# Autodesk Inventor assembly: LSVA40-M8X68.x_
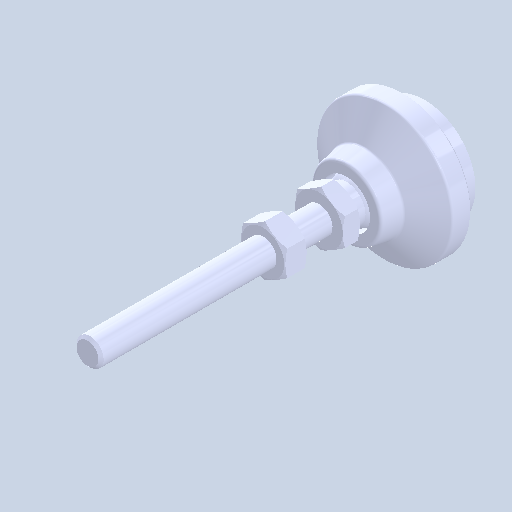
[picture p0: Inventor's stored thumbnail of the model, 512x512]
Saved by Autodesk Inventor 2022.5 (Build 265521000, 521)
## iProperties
Created: 2024-08
Part Number: LSVA40-M8X68.x_
Document SubType Name: Assembly
Designer: ImaoCorp
Author: ImaoCorp
Sending System: SOLIDWORKS 2022-2022290
MC: AMD64
MC_MODEL: Intel64 Family 6 Model 60 Stepping 3, GenuineIntel
OS: Windows_NT
FRU: Parasolid Version 33.1, build 260,  4-25-2022
FORMAT: text
GUISE: transmit
KEY: FILELSVA40-M8X68.x_t
DATE: Fri Aug 23 16:08:00 2024
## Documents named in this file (4)
- X:\14_SW2022-Inv2022\06_2024-10新製品(SME)\ELS_データ\l\lsva40-m8x68\LSVA40-M8X68.x_.iam
- X:\14_SW2022-Inv2022\06_2024-10新製品(SME)\ELS_データ\l\lsva40-m8x68\LSVA40-M8X68_01.ipt
- X:\14_SW2022-Inv2022\06_2024-10新製品(SME)\ELS_データ\l\lsva40-m8x68\LSVA40-M8X68_02.ipt
- X:\14_SW2022-Inv2022\06_2024-10新製品(SME)\ELS_データ\l\lsva40-m8x68\LSVA40-M8X68_03.ipt
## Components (3 placed, 3 different names)
1. LSVA40-M8X68_01
2. LSVA40-M8X68_02
3. LSVA40-M8X68_03
